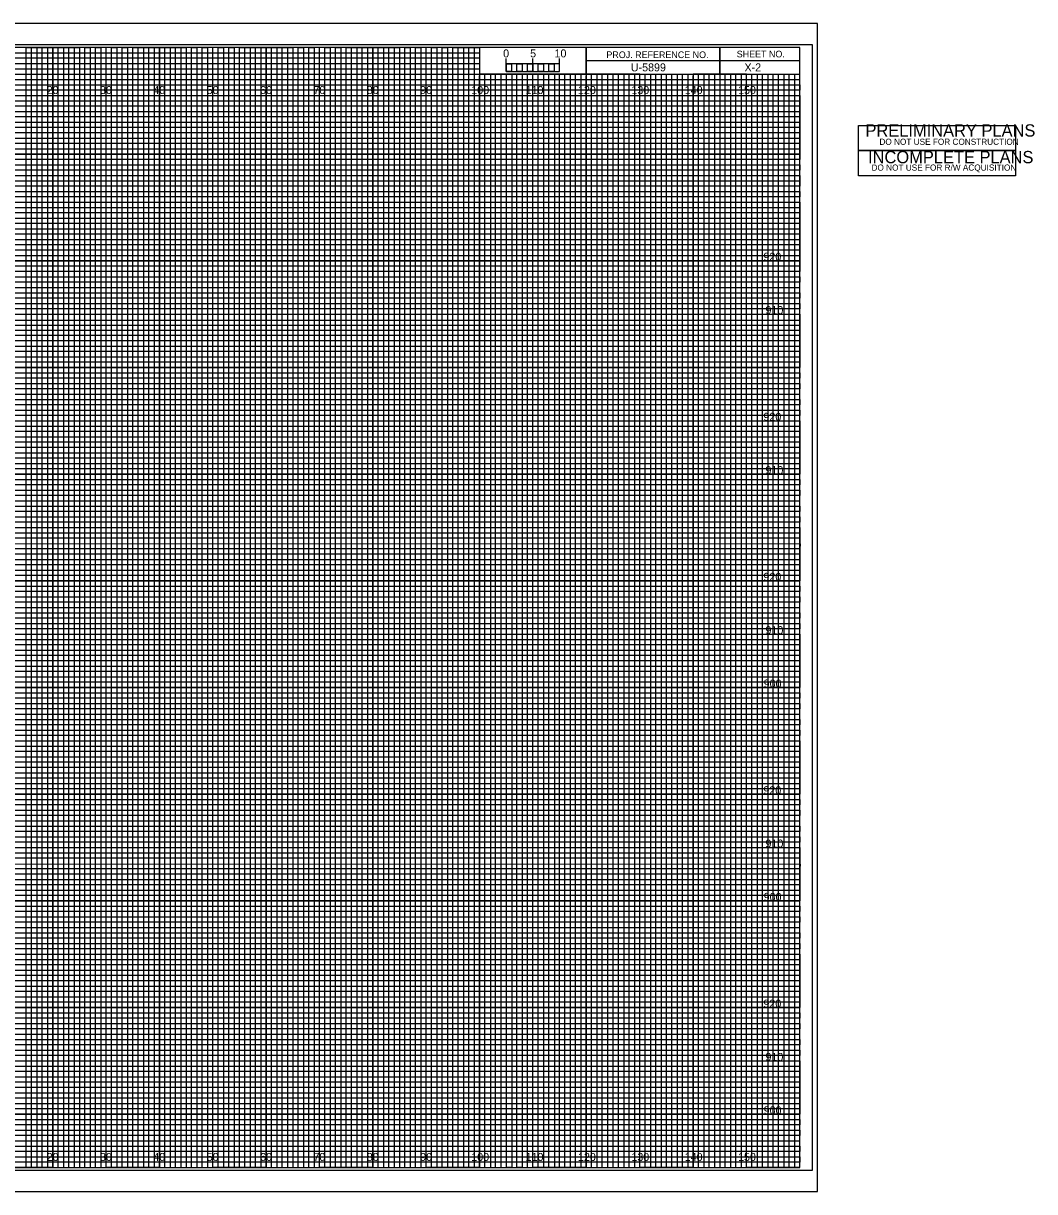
# Model space of a CAD drawing. Extents: x -13 to 364, y -4 to 214.
# Drawn here: x 174.5 to 364, y -4.5 to 214.5 of the extents above; entities that cross this region are included whole.
import ezdxf

# ---------------------------------------------------------------- set-up
doc = ezdxf.new("R2010")
doc.units = 0
for name, color, linetype in [('Prop SS Cut Line', 7, 'Continuous'), ('Prop SS Fill Line', 7, 'Continuous'), ('Prop XS Bar Scale Labels', 7, 'Continuous'), ('Prop XS Elevation Labels', 7, 'Continuous'), ('Prop XS Label Text', 7, 'Continuous'), ('Prop XS Project Number', 7, 'Continuous'), ('Prop XS Shear Point Label', 7, 'Continuous'), ('Prop XS Sheet Number', 7, 'Continuous'), ('Scratch_Level_3', 7, 'Continuous'), ('Sheet Cross Section Grid Minor 2 CELL', 7, 'Continuous'), ('Sheet Cross Section Scale CELL', 7, 'Continuous'), ('Sheet Cutting Line CELL', 7, 'Continuous'), ('Sheet DOT Grid CELL', 7, 'Continuous'), ('Sheet Plot Border Inside CELL', 7, 'Continuous'), ('Sheet Plot Border Outside CELL', 7, 'Continuous'), ('Sheet Sticker Incomplete CELL', 7, 'Continuous'), ('Sheet Sticker Preliminary CELL', 7, 'Continuous')]:
    doc.layers.add(name, color=color, linetype=linetype)

msp = doc.modelspace()

# ---------------------------------------------------------------- linework, layer by layer
at = {"layer": 'Prop SS Cut Line'}
for p, q in [((190, 210), (180, 210)), ((180, 210), (180, 0)), ((190, 0), (190, 210)), ((210, 210), (200, 210)), ((200, 210), (200, 0)), ((210, 0), (210, 210)), ((230, 210), (220, 210)), ((220, 210), (220, 0)), ((230, 0), (230, 210)), ((250, 210), (240, 210)), ((240, 210), (240, 0)), ((250, 0), (250, 210)), ((260, 210), (260, 0)), ((270, 0), (270, 205)), ((290, 205), (280, 205)), ((280, 205), (280, 0)), ((290, 0), (290, 205)), ((310, 205), (300, 205)), ((300, 205), (300, 0)), ((310, 0), (310, 205)), ((180, 0), (170, 0)), ((200, 0), (190, 0)), ((220, 0), (210, 0)), ((240, 0), (230, 0)), ((260, 0), (250, 0)), ((280, 0), (270, 0)), ((300, 0), (290, 0)), ((320, 0), (310, 0)), ((320, 0), (320, 0))]:
    msp.add_line(p, q, dxfattribs=at)
for points in [[(0, 200), (320, 200), (320, 190), (0, 190)], [(0, 180), (320, 180), (320, 170), (0, 170)], [(0, 160), (320, 160), (320, 150), (0, 150)], [(0, 140), (320, 140), (320, 130), (0, 130)], [(0, 120), (320, 120), (320, 110), (0, 110)], [(0, 100), (320, 100), (320, 90), (0, 90)], [(0, 80), (320, 80), (320, 70), (0, 70)], [(0, 60), (320, 60), (320, 50), (0, 50)], [(0, 40), (320, 40), (320, 30), (0, 30)], [(0, 20), (320, 20), (320, 10), (0, 10)]]:
    msp.add_lwpolyline(points, dxfattribs=at)
at = {"layer": 'Prop XS Label Text'}
for p, q in [((0, 209), (260, 209)), ((260, 209), (260, 207.98)), ((260, 207.98), (0, 207.98)), ((0, 207), (260, 207)), ((260, 205.89), (0, 205.89)), ((260, 207), (260, 205.89)), ((0, 204), (320, 204))]:
    msp.add_line(p, q, dxfattribs=at)
for points in [[(0, 203), (270, 203), (320, 203), (320, 202), (0, 202)], [(0, 201), (320, 201), (320, 199), (0, 199)], [(0, 198), (320, 198), (320, 197), (0, 196.98)], [(0, 196), (320, 196), (320, 194), (0, 194)], [(0, 193), (320, 193), (320, 192), (0, 192)], [(0, 191), (320, 191), (320, 189), (0, 189)], [(0, 188), (320, 188), (320, 187), (0, 187)], [(0, 186), (320, 186), (320, 184), (0, 184)], [(0, 183), (320, 183), (320, 182), (0, 182)], [(0, 181), (320, 181), (320, 179), (0, 179)], [(0, 178), (320, 178), (320, 177), (0, 177)], [(0, 176), (320, 176), (320, 173.95), (320, 173), (320, 172), (0, 172)], [(0, 174), (320, 174), (320, 173), (0, 173)], [(0, 171), (320, 171), (320, 169), (0, 169.03)], [(0, 169.03), (320, 169), (320, 168), (0, 168)], [(0, 167), (320, 167), (320, 166), (0, 166)], [(0, 164), (320, 164), (320, 163), (0, 163)], [(0, 162), (320, 162), (320, 161), (0, 161)], [(-0.07, 158.89), (320, 158.89), (320, 157.88), (-0.07, 157.88)], [(0, 157), (320, 157), (320, 156), (0, 156)], [(0, 154), (320, 154), (320, 153), (0, 153)], [(0, 152), (320, 152), (320, 151), (0, 151)], [(0, 149), (320, 149), (320, 148), (0, 148)], [(0, 147), (320, 147), (320, 146), (0, 146)], [(0, 144), (320, 144), (320, 143), (0, 143)], [(0, 142), (320, 142), (320, 141), (0, 141)], [(0, 139), (320, 139), (319.99, 137.98), (0, 138)], [(0, 137), (320, 137), (320, 136), (0, 136)], [(0, 134), (320, 134), (320, 133), (0, 133)], [(0, 132), (320, 132), (320, 131), (0, 131)], [(0, 129), (320, 129), (320, 128), (0, 128)], [(0, 127), (320, 127), (320, 126), (0, 126)], [(0, 124), (320, 124), (320, 123), (0, 123)], [(0, 122), (320, 122), (320, 121), (0, 121)], [(0, 119), (320, 119), (320, 118), (0, 118)], [(0, 116.99), (320.07, 116.91), (320, 116), (0, 116)], [(0, 114), (320, 114), (320, 113), (0, 113)], [(0, 112), (320, 112), (320, 111), (0, 111)], [(0, 109), (320, 109), (320, 108), (0, 108)], [(0, 107), (320, 107), (320, 106), (0, 106)], [(0, 104), (320, 104), (320, 103), (0, 103)], [(0, 102), (320, 102), (320, 101), (0, 101)], [(0, 99), (320, 99), (320, 98), (0, 98)], [(0, 97), (320, 97), (320, 96), (0, 96)], [(0, 94), (320, 94), (320, 93), (0, 93)], [(0, 92), (320, 92), (320, 91), (0, 91)], [(0, 89), (320, 89), (320, 88), (0, 88)], [(0, 87), (320, 87), (320, 86), (0, 86)], [(0, 84), (320, 84), (320, 83), (0, 83)], [(0, 82), (320, 82), (320, 81), (0, 81)], [(0, 79), (320, 79), (319.99, 77.98), (0, 78)], [(0, 77), (320, 77), (320, 76), (0, 76)], [(0, 74), (320, 74), (320, 73), (0, 73)], [(0, 72), (320, 72), (320, 71), (0, 71)], [(0, 69), (320, 69), (320, 68), (0, 68)], [(0, 67), (320, 67), (320, 66), (0, 66)], [(0, 64), (320, 64), (320, 63), (0, 63)], [(0, 62), (320, 62), (320, 61), (0, 61)], [(0, 59), (320, 59), (320, 58), (0, 58)], [(0, 56.99), (320.07, 56.91), (320, 56), (0, 56)], [(0, 54), (320, 54), (320, 53), (0, 53)], [(0, 52), (320, 52), (320, 51), (0, 51)], [(0, 49), (320, 49), (320, 48), (0, 48)], [(0, 47), (320, 47), (320, 46), (0, 46)], [(0, 44), (320, 44), (320, 43), (0, 43)], [(0, 42), (320, 42), (320, 41), (0, 41)], [(0, 39), (320, 39), (320, 38), (0, 38)], [(0, 37), (320, 37), (320, 36), (0, 36)], [(0, 34), (320, 34), (320, 33), (0, 33)], [(0, 32), (320, 32), (320, 31), (0, 31)], [(0, 29), (320, 29), (320, 28), (0, 28)], [(0, 27), (320, 27), (320, 26), (0, 26)], [(0, 24), (320, 24), (320, 23), (0, 23)], [(0, 22), (320, 22), (320, 21), (0, 21)], [(0, 19), (320, 19), (320, 18), (0, 18)], [(0, 17), (320, 17), (320, 16), (0, 16)], [(0, 14), (320, 14), (320, 13), (0, 13)], [(0, 12), (320, 12), (320, 11), (0, 11)], [(0, 9), (320, 9), (320, 8), (0, 8)], [(0, 7), (320, 7), (320, 6), (0, 6)], [(0, 4), (320, 4), (320, 3), (0, 3)], [(0, 2), (320, 2), (320, 1), (0, 1)]]:
    msp.add_lwpolyline(points, dxfattribs=at)
at = {"layer": 'Prop XS Shear Point Label'}
for points in [[(165, 0), (175, 0), (175, 210), (185, 210), (185, 0), (195, 0), (195, 210), (205, 210), (205, 0), (215, 0), (215, 210), (225, 210), (225, 0), (235, 0), (235, 210), (245, 210), (245, 0), (255, 0), (255, 210), (259.93, 210), (260, 210), (260, 205), (264.99, 205), (264.99, 0), (275, 0), (275, 205), (285, 205), (285, 0), (295, 0), (295, 205), (305, 205), (305, 0), (315, 0), (315, 205)], [(0, 205), (275, 205)], [(0, 185), (320, 185), (320, 195), (0, 195)], [(0, 165), (320, 165), (320, 175), (0, 175)], [(0, 145), (320, 145), (320, 155), (0, 155)], [(0, 125), (320, 125), (320, 135), (0, 135)], [(0, 105), (320, 105), (320, 115), (0, 115)], [(0, 85), (320, 85), (320, 95), (0, 95)], [(0, 65), (320, 65), (320, 75), (0, 75)], [(0, 45), (320, 45), (320, 55), (0, 55)], [(0, 25), (320, 25), (320, 35), (0, 35)], [(0, 5), (320, 5), (320, 15), (0, 15)]]:
    msp.add_lwpolyline(points, dxfattribs=at)
at = {"layer": 'Scratch_Level_3'}
for p, q in [((305, 210), (305, 205)), ((305, 205), (305, 210)), ((280, 207.5), (280, 205)), ((320, 207.49), (280, 207.49)), ((280, 205), (320, 205))]:
    msp.add_line(p, q, dxfattribs=at)
for points in [[(320, 210), (0, 210), (0, 0), (320, 0)], [(280, 210), (260, 210), (260, 205.03), (280, 205.03)], [(320, 210), (280, 210), (280, 205), (320, 205)]]:
    msp.add_lwpolyline(points, close=True, dxfattribs=at)
at = {"layer": 'Sheet Cross Section Grid Minor 2 CELL'}
for p, q in [((267, 205), (266.01, 205)), ((266.01, 205), (266.01, 0)), ((267, 0), (267, 205)), ((269, 205), (268, 205)), ((268, 205), (268, 0)), ((269, 0), (269, 205)), ((266.01, 0), (265, 0)), ((268, 0), (267, 0))]:
    msp.add_line(p, q, dxfattribs=at)
for points in [[(175, 0), (176, 0), (176, 210), (177, 210), (177, 0)], [(177, 0), (178, 0), (178, 210), (179, 210), (179, 0)], [(180, 0), (181, 0), (181, 210), (182, 210), (182, 0)], [(182, 0), (183, 0), (183, 210), (184, 210), (184, 0)], [(185, 0), (186, 0), (186, 210), (187, 210), (187, 0)], [(187, 0), (188, 0), (188, 210), (189, 210), (189, 0)], [(190, 0), (191, 0), (191, 210), (192, 210), (192, 0)], [(192, 0), (193, 0), (193, 210), (194, 210), (194, 0)], [(195, 0), (196, 0), (196, 210), (197, 210), (197, 0)], [(197, 0), (198, 0), (198, 210), (199, 210), (199, 0)], [(200, 0), (201, 0), (201, 210), (202, 210), (202, 0)], [(202, 0), (203, 0), (203, 210), (204, 210), (204, 0)], [(205, 0), (206, 0), (206, 210), (207, 210), (207, 0)], [(207, 0), (208, 0), (208, 210), (209, 210), (209, 0)], [(210, 0), (211, 0), (211, 210), (212, 210), (212, 0)], [(212, 0), (213, 0), (213, 210), (214, 210), (214, 0)], [(215, 0), (216, 0), (216, 210), (217, 210), (217, 0)], [(217, 0), (218, 0), (218, 210), (219, 210), (219, 0)], [(220, 0), (221, 0), (221, 210), (222, 210), (222, 0)], [(222, 0), (223, 0), (223, 210), (224, 210), (224, 0)], [(225, 0), (226, 0), (226, 210), (227, 210), (227, 0)], [(227, 0), (228, 0), (228, 210), (229, 210), (229, 0)], [(230, 0), (231, 0), (231, 210), (232, 210), (232, 0)], [(232, 0), (233, 0), (233, 210), (234, 210), (234, 0)], [(235, 0), (236, 0), (236, 210), (237, 210), (237, 0)], [(237, 0), (238, 0), (238, 210), (239, 210), (239, 0)], [(240, 0), (241, 0), (241, 210), (242, 210), (242, 0)], [(242, 0), (243, 0), (243, 210), (244, 210), (244, 0)], [(245, 0), (246, 0), (246, 210), (247, 210), (247, 0)], [(247, 0), (248, 0), (248, 210), (249, 210), (249, 0)], [(250, 0), (251, 0), (251, 210), (252, 210), (252, 0)], [(252, 0), (253, 0), (253, 210), (254, 210), (254, 0)], [(255, 0), (256, 0), (256, 210), (257, 210), (257, 0)], [(257, 0), (258, 0), (258, 210), (259, 210), (259, 0)], [(260, 0), (261, 0), (261, 205), (262.02, 205), (262.02, 0)], [(262, 0), (263, 0), (263, 205), (263.99, 205), (263.99, 0)], [(270, 0), (270.98, 0), (270.98, 205), (272, 205), (272, 0)], [(272, 0), (273, 0), (273, 205), (274.05, 205), (274.05, 0)], [(275, 0), (276, 0), (276, 205), (277, 205), (277, 0)], [(277, 0), (278, 0), (278, 205), (279, 205), (279, 0)], [(280, 0), (281, 0), (281, 205), (282, 205), (282, 0)], [(282, 0), (283, 0), (283, 205), (284, 205), (284, 0)], [(285, 0), (286, 0), (286, 205), (287, 205), (287, 0)], [(287, 0), (288, 0), (288, 205), (289, 205), (289, 0)], [(290, 0), (291, 0), (291, 205), (292, 205), (292, 0)], [(292, 0), (293, 0), (293, 205), (294, 205), (294, 0)], [(295, 0), (296, 0), (296, 205), (297, 205), (297, 0)], [(297, 0), (298, 0), (298, 205), (299, 205), (299, 0)], [(300, 0), (301, 0), (301, 205), (302, 205), (302, 0)], [(302, 0), (303, 0), (303, 205), (304, 205), (304, 0)], [(305, 0), (306, 0), (306, 205), (307, 205), (307, 0)], [(307, 0), (308, 0), (308, 205), (309, 205), (309, 0)], [(310, 0), (311, 0), (311, 205), (312, 205), (312, 0)], [(312, 0), (313, 0), (313, 205), (314, 205), (314, 0)], [(315, 0), (316, 0), (316, 205), (317, 205), (317, 0)], [(317, 0), (318, 0), (318, 205), (319, 205), (319, 0)]]:
    msp.add_lwpolyline(points, dxfattribs=at)
at = {"layer": 'Sheet Cross Section Scale CELL'}
for p, q in [((265, 205.49), (265, 207.9)), ((265, 206.9), (265, 207.9)), ((270, 205.49), (270, 207.9)), ((275, 205.49), (275, 207.9)), ((275, 206.9), (275, 207.9))]:
    msp.add_line(p, q, dxfattribs=at)
for points in [[(275, 206.9), (265, 206.9), (265, 205.49), (275, 205.49)], [(265, 206.9), (266, 206.9), (266, 205.49), (265, 205.49)], [(267, 206.9), (268, 206.9), (268, 205.49), (267, 205.49)], [(269, 206.9), (270, 206.9), (270, 205.49), (269, 205.49)], [(271, 206.9), (272, 206.9), (272, 205.49), (271, 205.49)], [(273, 206.9), (274, 206.9), (274, 205.49), (273, 205.49)]]:
    msp.add_lwpolyline(points, close=True, dxfattribs=at)
at = {"layer": 'Sheet Cutting Line CELL'}
for p, q in [((323.3, 214.5), (-13.4, 214.5)), ((-13.4, -4.5), (323.3, -4.5))]:
    msp.add_line(p, q, dxfattribs=at)
at = {"layer": 'Sheet DOT Grid CELL'}
for p, q in [((180, 0), (180, 210)), ((190, 0), (190, 210)), ((200, 0), (200, 210)), ((210, 0), (210, 210)), ((220, 0), (220, 210)), ((230, 0), (230, 210)), ((240, 0), (240, 210)), ((250, 0), (250, 210)), ((260, 0), (260, 204.69)), ((270, 0), (270, 204.69)), ((280, 0), (280, 204.69)), ((290, 0), (290, 204.69)), ((300, 0), (300, 204.69)), ((310, 0), (310, 204.69)), ((0, 200), (320, 200)), ((0, 190), (320, 190)), ((0, 180), (320, 180)), ((0, 170), (320, 170)), ((0, 160), (320, 160)), ((0, 150), (320, 150)), ((0, 140), (320, 140)), ((0, 130), (320, 130)), ((0, 120), (320, 120)), ((0, 110), (320, 110)), ((0, 100), (320, 100)), ((0, 90), (320, 90)), ((0, 80), (320, 80)), ((0, 70), (320, 70)), ((0, 60), (320, 60)), ((0, 50), (320, 50)), ((0, 40), (320, 40)), ((0, 30), (320, 30)), ((0, 20), (320, 20)), ((0, 10), (320, 10))]:
    msp.add_line(p, q, dxfattribs=at)
at = {"layer": 'Sheet Plot Border Inside CELL'}
msp.add_lwpolyline([(-10.8, -0.5), (322.4, -0.5), (322.4, 210.5), (-10.8, 210.5)], close=True, dxfattribs=at)
at = {"layer": 'Sheet Plot Border Outside CELL'}
msp.add_lwpolyline([(-13.4, -4.5), (323.3, -4.5), (323.3, 214.5), (-13.4, 214.5)], close=True, dxfattribs=at)
at = {"layer": 'Sheet Sticker Incomplete CELL'}
msp.add_lwpolyline([(331.01, 185.94), (331.01, 190.64), (360.41, 190.64), (360.41, 185.94)], close=True, dxfattribs=at)
at = {"layer": 'Sheet Sticker Preliminary CELL'}
msp.add_lwpolyline([(331.01, 190.64), (331.01, 195.34), (360.41, 195.34), (360.41, 190.64)], close=True, dxfattribs=at)

# ---------------------------------------------------------------- texts
at = {"layer": 'Prop SS Fill Line'}
for s, p in [('20', (178.86, 201.25)), ('30', (188.86, 201.25)), ('40', (198.86, 201.25)), ('50', (208.86, 201.25)), ('60', (218.86, 201.25)), ('70', (228.86, 201.25)), ('80', (238.86, 201.25)), ('90', (248.86, 201.25)), ('100', (258.44, 201.25)), ('110', (268.62, 201.25)), ('120', (278.44, 201.25)), ('130', (288.44, 201.25)), ('140', (298.44, 201.25)), ('150', (308.44, 201.25)), ('20', (178.86, 1.25)), ('30', (188.86, 1.25)), ('40', (198.86, 1.25)), ('50', (208.86, 1.25)), ('60', (218.86, 1.25)), ('70', (228.86, 1.25)), ('80', (238.86, 1.25)), ('90', (248.86, 1.25)), ('100', (258.44, 1.25)), ('110', (268.62, 1.25)), ('120', (278.44, 1.25)), ('130', (288.44, 1.25)), ('140', (298.44, 1.25)), ('150', (308.44, 1.25))]:
    msp.add_text(s, height=1.5, dxfattribs=at).set_placement(p)
at = {"layer": 'Prop XS Bar Scale Labels'}
for s, p in [('5', (269.47, 208.12)), ('10', (274.04, 208.12))]:
    msp.add_text(s, height=1.5, dxfattribs=at).set_placement(p)
at = {"layer": 'Prop XS Elevation Labels'}
for s, p in [('920', (313.19, 170)), ('910', (313.57, 160)), ('920', (313.19, 140)), ('910', (313.57, 130)), ('920', (313.19, 110)), ('910', (313.57, 100)), ('900', (313.24, 90)), ('920', (313.19, 70)), ('910', (313.57, 60)), ('900', (313.24, 50)), ('920', (313.19, 30)), ('910', (313.57, 20)), ('900', (313.24, 10))]:
    msp.add_text(s, height=1.5, dxfattribs=at).set_placement(p)
at = {"layer": 'Prop XS Project Number'}
msp.add_text('U-5899', height=1.5, dxfattribs=at).set_placement((288.34, 205.5))
at = {"layer": 'Prop XS Sheet Number'}
msp.add_text('X-2', height=1.5, dxfattribs=at).set_placement((309.64, 205.5))
at = {"layer": 'Scratch_Level_3'}
for s, p in [('PROJ. REFERENCE NO.', (283.77, 207.99)), ('SHEET NO.', (308.19, 208.12))]:
    msp.add_text(s, height=1.25, dxfattribs=at).set_placement(p)
at = {"layer": 'Sheet Cross Section Scale CELL'}
msp.add_text('0', height=1.5, dxfattribs=at).set_placement((264.41, 208.12))
at = {"layer": 'Sheet Sticker Incomplete CELL'}
for s, height, p in [('INCOMPLETE PLANS', 2.304, (332.8, 188.28)), ('DO NOT USE FOR R/W ACQUISITION', 1.152, (333.45, 186.89))]:
    msp.add_text(s, height=height, dxfattribs=at).set_placement(p)
at = {"layer": 'Sheet Sticker Preliminary CELL'}
for s, height, p in [('PRELIMINARY PLANS', 2.304, (332.31, 193.27)), ('DO NOT USE FOR CONSTRUCTION', 1.152, (334.93, 191.73))]:
    msp.add_text(s, height=height, dxfattribs=at).set_placement(p)

doc.saveas('drawing.dxf')
